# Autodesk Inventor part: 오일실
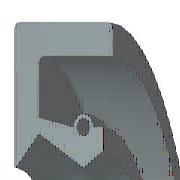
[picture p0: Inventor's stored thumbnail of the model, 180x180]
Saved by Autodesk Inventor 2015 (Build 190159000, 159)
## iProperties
Created: 2015-11
Part Number: 오일실
Material: 고무
Description: 오일-실
Document SubType Name: Modeling
Standard: KS B 2804
Designer: mdu
Standards Organization: KS
Language: ko-KR
Size Designation: D - 10 20 7
Categories: <MemberInstance><Categories><Category DisplayName="샤프트 부품" InternalName="7f7aeb1f-a693-4053-b835-cee3144e0d98" Mnemonic="SHFT"><Category DisplayName="실링" Intern
Density: 0.93 g/cm^3
Appearance: 고무 - 검은색 - 버전 1.1
Mass: 1.11329 g
Surface Area: 16.3871 cm^2
Volume: 1.19708 cm^3
IsCustomPart: 0
Author: mdu
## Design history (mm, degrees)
revolve "본체" stored, may be unused: angle "d17" = 90 deg
revolve "스프링1" stored, may be unused: angle "d18" = 90 deg
body "Solid1"
sketch "스케치1"
  geometry: L1 (0, 10)-(7, 10); L2 (7, 8.25)-(1.75, 8.25); L3 (1.75, 6.75)-(4.9, 5); L4 (4.9, 5)-(0, 5); L5 (0, 0)-(9.586, 0) reference; L6 (4.9, 5)-(6.3, 5.875); L7 (0, 18)-(0, -3) reference; L8 (-1.941, 0)-(11.507, 0) reference; L9 (4.2, 7.1)-(1.75, 7.59); L10 (1.75, 7.59)-(1.75, 8.25); L11 (0, 10)-(0, 5.088); L12 (4.9, 5)-(0, 5); L13 (1.75, 6.75)-(0.152, 5.028); L14 (7, 10)-(7, 8.25); L15 (5.6, 7.1)-(6.3, 7.1); L16 (6.3, 7.1)-(6.3, 5.875); C1 r 0.455 at (4.9, 7.1); A1 r 0.7 centre (4.9, 7.1) between (5.6, 7.1) and (4.2, 7.1); A2 r 0.088 centre (0.088, 5.088) between (0, 5.088) and (0.152, 5.028); 1 further point
  constraints: 28 end point, 5 horizontal alignment, 5 point on line, 4 point on circle, 4 vertical alignment, 3 centre point, 3 tangent, 2 collinear, 2 horizontal, 2 perpendicular, 1 coincident, 1 parallel
  dimensions: "d0" = 20 diameter of L1 L5 (= SD2); "d1" = 1.75 distance of L1.end L2.start (= SD); "d2" = 0.91 diameter of C1 (= SPDI); "d3" = 1.4 diameter of A1 (= SPDA); "d4" = 10 diameter of L3.end L5 (= NND); "d5" = 13.5 diameter of L3.start L5 (= TKDM); "d7" = 15.18 diameter of L9.end L5 (= TKDM + 0.24 x SWDT); "d8" = 1.75 distance between parallel lines of L11 L10 (= SD); "d9" = 4.9 distance from line of L11 C1.centre (= SPDST); "d10" = 14.2 diameter of C1.centre L5 (= HLDM); "d11" = 0.0875 radius of A2 (= 0.25 x LAB); "d12" = 6.3 distance between parallel lines of L11 L16 (= SDI); "d13" = 11.75 diameter of L6.end L5 (= ABDM); "d14" = 7 distance from line of L11 L1.end (= SWDT)
fillet "모깎기1" dims "d6" = 0.3 (= RR)
other parameters: "SD2" = 20 [user parameter; used in 1 equation term], "SWDT" = 7 [user parameter; used in 2 equation terms], "RR" = 0.3 [user parameter; used in 1 equation term], "SD" = 1.75 [user parameter; used in 2 equation terms], "NND" = 10 [user parameter; used in 1 equation term], "SPDA" = 1.4 [user parameter; used in 1 equation term], "SPDI" = 0.91 [user parameter; used in 1 equation term], "TKDM" = 13.5 [user parameter; used in 2 equation terms], "HLDM" = 14.2 [user parameter; used in 1 equation term], "ABDM" = 11.75 [user parameter; used in 1 equation term], "SDI" = 6.3 [user parameter; used in 1 equation term], "SPDST" = 4.9 [user parameter; used in 1 equation term], "LAB" = 0.35 [user parameter; used in 1 equation term], "d15" = 0, "d16" = 0, "d19" = 0
